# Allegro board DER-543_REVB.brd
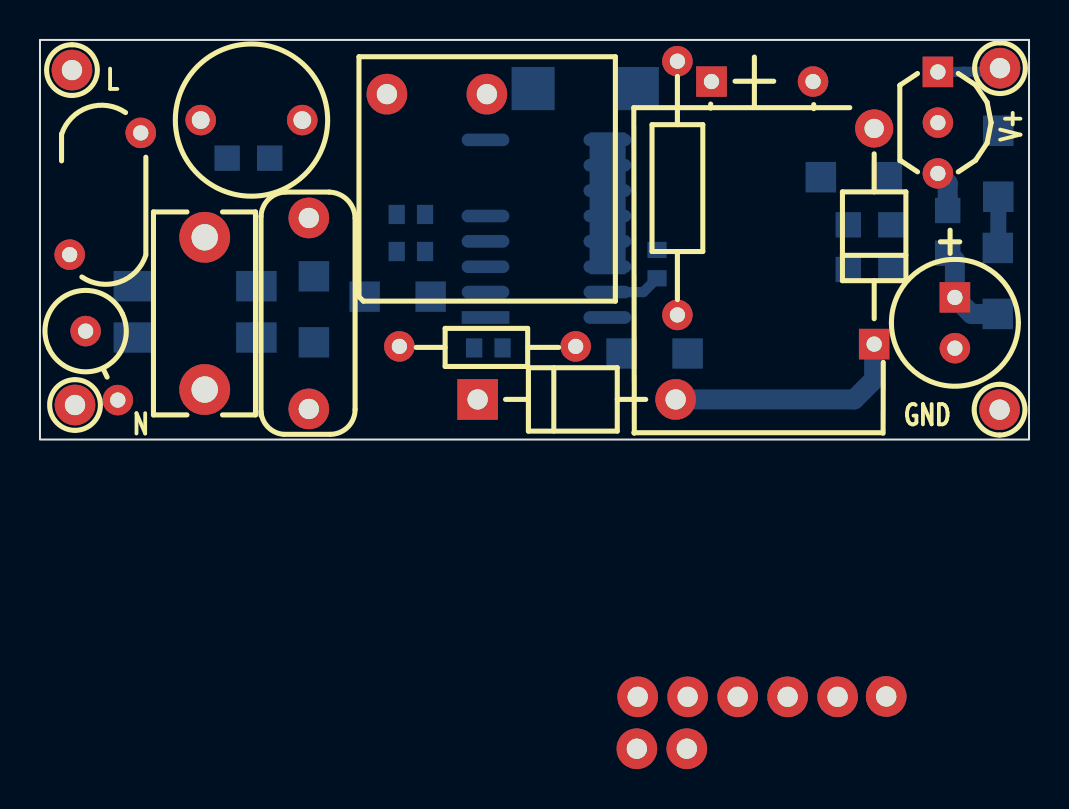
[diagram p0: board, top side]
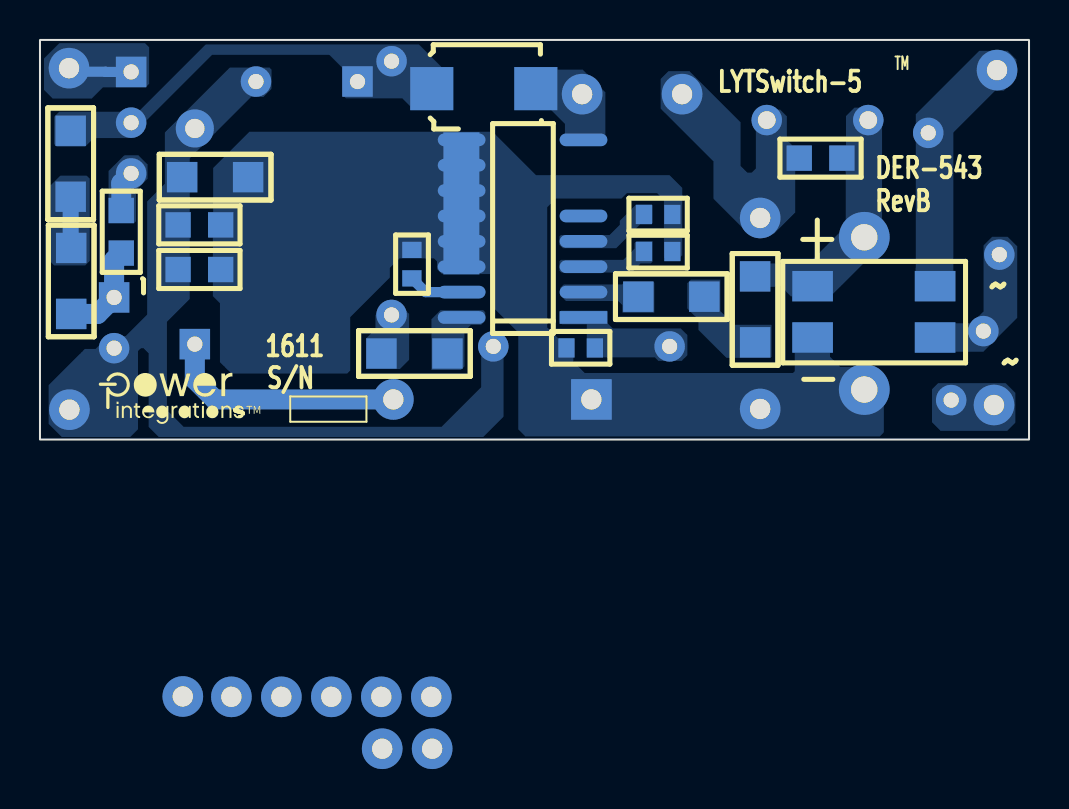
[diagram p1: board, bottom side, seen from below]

Outline 49.48 x 20 mm; copper layers: TOP, BOTTOM. Coordinates in mm from the lower left corner of the outline.
Outline path: rectangle 0,0 49.48,20

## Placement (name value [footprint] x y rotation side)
BR1  B10S-G  [PISMSOIC4]  4.7 5.11 90 bottom
C1  150 nF  [PINPCAPRAD500X200400040]  13.42 11.41 270 top
C2  47 nF  [PI_NP395X200LS300D040]  8.24 10.12 270 top
C4  22 uF  [PIPOLCAPCLYD500LS200040]  33.59 19.42 0 top
C6  2.2 uF  [PISMC0603]  30.87 8.07 90 bottom
C7  180 nF  [PISMC0603]  21.72 4.58 0 bottom
C11  2.2 uF  [PIPOLCAPCYLD250LS100030]  45.77 7.11 270 top
C12  10 uF  [PISMC0805]  42.57 8.51 180 bottom
D1  MURS160T3G  [PISMSMB]  29.88 17.56 180 bottom
D2  1N4001  [PIDV200X110X040DO41]  21.89 2.01 0 top
D3  1N4001  [PIDV200X110X040DO41#2]  41.73 4.78 90 top
F1  5 A  [PI_V_AXIAL_160LS150D030]  2.28 5.43 295 top
L1  3.3 mH  [PICHOKE030DIALS200035]  8.04 15.99 0 top
NOREF  -  []  -150.78 54.23 0 top
NOREF#2  -  []  -228.6 -144.78 0 top
NOREF#3  -  []  0 0 0 top
NOREF#4  -  []  49.48 0 90 top
NOREF#5  -  []  47.09 3.25 180 bottom
Q1  STX13003-AP  [PITO92R100]  44.92 18.4 270 top
R1  10 k  [PISMR0805]  9.36 14.08 0 bottom
R2  2.00 M  [PISMR1206]  13.7 8.17 270 bottom
R3  2.00 M  [PISMR1206]  16.24 7.15 0 bottom
R4  3 k  [PISMR1206]  47.94 15.46 270 bottom
R5  1.6 M  [PI14WVRESD100LS100D030]  31.89 18.94 270 top
R6  3 k  [PISMR1206]  47.92 9.59 270 bottom
R7  1 k  [PISMR0805]  45.41 11.47 270 bottom
R8  1.60 M  [PISMR1206]  29.1 4.31 0 bottom
R9  6.04 k  [PISMR0603]  19.27 9.41 180 bottom
R10  24 k  [PISMR0603]  19.27 11.26 180 bottom
R11  39 k  [PI18WVRESD80LS100D030]  18.58 4.66 0 top
R14  5.49 R  [PISMR1206]  39.07 13.13 0 bottom
R15  10 k  [PISMR0805]  40.44 10.74 0 bottom
RV1  275 Vac  [PIDISC350X160LS210X140040]  1.49 9.25 90 top
T1  EE13  [PI_BOBBIN_EE13V_10P]  17.36 8.79 0 top
TP1  WHT  [PITPKEYSTONE100X100]  1.75 1.73 0 top
TP2  RED  [PITPKEYSTONE100X100]  48.03 18.59 0 top
TP3  WHT  [PITPKEYSTONE100X100]  1.6 18.49 0 top
TP4  BLK  [PITPKEYSTONE100X100]  48.01 1.49 0 top
U1  LYT5225D  [PI_SMD_SO_14-16P_SHORT9-14]  22.29 6.11 90 bottom

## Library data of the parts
BR1 = DIODE BRIDGE_~~+-: alternate symbols: (pi_sm_soic4_slot)
C1 C2 C6 C7 C12 = CAP NP
C4 = CAP POL: alternate symbols: (pipolcapclyd500ls200040630lh)
C11 = CAP POL: alternate symbols: (pipolcapcyld250ls100030h)
D1 = DIODE
D2 D3 = DIODE: alternate symbols: (pidax475x125040do41,pidv200x110x040do41wbead,pidax390x125040do41)
F1 = FUSE
L1 = INDUCTOR: alternate symbols: (pi_choke_450hx375ls197d030_h)
Q1 = NPN_ECB: alternate symbols: (PIT092100)
R1-R4 R6-R10 R14 R15 = R
R5 = R: alternate symbols: (pi14wvresd100ls200d030,pi14wresd100ls400d030,pi14wresd100ls500d030)
R11 = R: alternate symbols: (pi18wresd080ls300d030)
RV1 = VARISTOR
T1 = BEE13/10PINS/GENERIC
TP1-TP4 = TESTPOINT
U1 = LYTSW-5_SO-16

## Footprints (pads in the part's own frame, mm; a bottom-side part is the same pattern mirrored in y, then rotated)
PI14WVRESD100LS100D030
  round 1.524 hole 0.762: 1(0,0) 2(12.7,0)
PI18WVRESD80LS100D030
  round 1.524 hole 0.762: 1(-0.6,0) 2(8.22,0)
PI_BOBBIN_EE13V_10P
  round 2.032 hole 1.016: 1(12.548,-21.666) 2(15.047,-21.666) 3(17.549,-21.666) 4(20.048,-21.666) 5(22.548,-21.666) 6(15.004,-24.265) 7(12.504,-24.265) 8(5.001,8.501) 9(24.978,-21.648) 10(0,8.501)
PI_NP395X200LS300D040
  round 2.54 hole 1.321: 1(0,0) 2(7.62,0)
PI_SMD_SO_14-16P_SHORT9-14
  rect 0.635x2.388 smd: 1(0,0)
  oval 0.635x2.388 smd: 2(1.27,0) 3(2.54,0) 4(3.81,0) 5(5.08,0) 8(8.89,0) 9(8.89,6.096) 10(7.62,6.096) 11(6.35,6.096) 12(5.08,6.096) 13(3.81,6.096) 14(2.54,6.096) 15(1.27,6.096) 16(0,6.096)
PI_V_AXIAL_160LS150D030
  round 1.524 hole 0.762: 1(0,0) 2(3.81,0)
PICHOKE030DIALS200035
  round 1.524 hole 0.889: 1(0,0) 2(5.08,0)
PIDISC350X160LS210X140040
  round 1.524 hole 0.762: 1(0,0) 2(6.096,-3.556)
PIDV200X110X040DO41
  rect 2.032x2.032 hole 1.016: 1(0,0)
  round 2.032 hole 1.016: 2(9.906,0)
PIDV200X110X040DO41#2
  rect 1.524x1.524 hole 0.762: 1(0,0)
  round 1.905 hole 0.965: 2(10.795,0)
PINPCAPRAD500X200400040
  round 2.032 hole 1.016: 1(0.325,0.025) 2(9.885,0.025)
PIPOLCAPCLYD500LS200040
  rect 1.524x1.524 hole 0.762: 1(0,-1.5)
  round 1.524 hole 0.762: 2(5.08,-1.5)
PIPOLCAPCYLD250LS100030
  rect 1.524x1.524 hole 0.762: 1(0,0)
  round 1.524 hole 0.762: 2(2.54,0)
PISMC0603
  rect 0.813x0.965 smd: 1(0,0) 2(1.422,0)
PISMC0805
  rect 1.27x1.27 smd: 1(0,0) 2(2.134,0)
PISMR0603
  rect 0.813x0.965 smd: 1(0,0) 2(1.422,0)
PISMR0805
  rect 1.27x1.27 smd: 1(0,0) 2(2.134,0)
PISMR1206
  rect 1.524x1.524 smd: 1(0,0) 2(3.302,0)
PISMSMB
  rect 2.159x2.159 smd: 1(0,0) 2(5.207,0)
PISMSOIC4
  rect 1.524x2.032 smd: 1(0,0) 2(2.571,0) 3(2.571,6.129) 4(0,6.129)
PITO92R100
  rect 1.524x1.524 hole 0.762: 1(0,0)
  round 1.524 hole 0.762: 2(2.54,0) 3(5.08,0)
PITPKEYSTONE100X100
  round 2.032 hole 1.016: 1(0,0)

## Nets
GND: BR1.4 C1.2 C2.2 C6.2 C7.2 C12.2 D2.1 R9.2 R10.2 R14.1 R15.1 U1.9(S) U1.10(SOURCE10) U1.11(SOURCE11) U1.12(SOURCE12) U1.13(SOURCE13) U1.14(SOURCE14)
N3973903: BR1.2 RV1.2 TP3.1
N3973993: BR1.3 C2.1 L1.1 R1.1 R2.1
N3974133: C4.1 D1.1 Q1.2(COLLECTOR) R4.1 R5.1
N3975245: C1.1 L1.2 R1.2 T1.10
N3976866: F1.2 TP1.1
N3988573: C7.1 R11.1 U1.1(FB)
N3988655: R10.1 U1.4(DS)
N3988764: R9.1 U1.3(DO)
N4093437: BR1.1 F1.1 RV1.1
N4116147: C6.1 U1.15(BP)
N4143937: R2.2 R3.1
N4145625: R3.2 U1.2(L)
N4152865: D1.2 T1.8 U1.8(D)
N4154298: C4.2 C11.2 C12.1 D3.2 R11.2 R14.2 R15.2 TP4.1
N4154621: R8.1 U1.16(OC)
N4279554: Q1.1(EMITTER) TP2.1
N4283675: C11.1 R6.2 R7.2
N4283879: Q1.3(BASE) R7.1
N4293995: D2.2 D3.1
N4302369: R4.2 R6.1
N4302480: R5.2 R8.2

Pads without a net: T1 1 2 3 4 5 6 7 9; U1 5

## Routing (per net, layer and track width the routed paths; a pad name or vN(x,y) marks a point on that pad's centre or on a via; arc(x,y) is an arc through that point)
N4116147: length 2.8
  BOTTOM w0.508: C6.1 30.19,7.38 U1.15
N4279554: length 3
  BOTTOM w0.508: Q1.1 46.19,18.4 46.2,18.41 47.95,18.41
N4283675: length 4.9
  BOTTOM w1: R7.2 45.77,8.97 C11.1 46.6,6.29 R6.2
N4283879: length 2.1
  BOTTOM w1: R7.1 45.41,12.83 Q1.3
N4293995: length 12.1
  BOTTOM w1: D2.2 40.73,2.01 41.73,3.01 D3.1
N4302369: length 2.6
  BOTTOM w0.8: R4.2 47.94,9.61 R6.1

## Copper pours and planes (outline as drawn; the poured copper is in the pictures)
GND on BOTTOM (solid shape): 29.3,8.27 27.5,8.27 27.5,15.38 29.3,15.38
GND on BOTTOM: 7.47,0.15 7.26,0.36 7.26,2.82 8.08,3.63 9.45,3.63 9.96,4.14 9.96,5.46 10.29,5.79 11.66,5.79 11.72,5.73 11.72,3.42 11.81,3.33 22.23,3.33 22.8,3.9 22.8,4.81 23.01,5.03 23.52,5.03 24.1,5.61 24.1,11.62 23.67,12.06 20.39,12.06 20.12,12.33 18.61,12.33 18.26,11.99 18.26,9.14 18.14,9.02 17.55,9.02 17.35,9.22 17.35,12.6 17.98,13.23 24.66,13.23 26.84,15.41 39,15.41 40.82,13.59 40.82,10.44 40.83,10.43 40.83,7.18 40.47,6.82 40.47,3.87 39.9,3.3 34.11,3.3 33.96,3.45 33.96,6.12 31.98,8.1 31.98,8.59 31.5,9.07 29.77,9.07 29.62,8.92 29.62,8.53 29.39,8.31 29.39,8.28 26.94,8.28 26.73,8.08 26.73,6.54 25.55,5.36 25.55,0.51 25.2,0.15
N3973903 on BOTTOM: 2.49,19.46 5.66,16.28 5.66,8.61 5.68,8.6 5.68,7.06 3.96,7.06 3.78,7.24 3.78,15.37 1.69,17.46 1.26,17.46 0.64,18.08 0.64,19.02 1.07,19.46
N3973993 on BOTTOM: 11.02,8.81 9.17,10.67 9.17,13.41 9.32,13.56 9.63,13.56 9.83,13.77 9.83,14.43 9.73,14.53 9.27,14.53 9.16,14.64 9.16,16.19 8.74,16.61 7.7,16.61 7.35,16.27 7.35,10.66 7.37,10.64 7.37,9.73 9.93,7.16 11.91,7.16 12.4,7.65 14.25,7.65 14.38,7.77 14.38,8.81
N3974133 on BOTTOM: 30.91,16.64 29.74,16.64 29.72,16.66 29.59,16.66 29.41,16.84 29.41,18.67 30.52,19.77 41.19,19.77 44.55,16.41 48.51,16.41 48.77,16.15 48.77,14.78 48.64,14.66 47.22,14.66 46.79,15.09 45.03,15.09 40.87,19.25 35,19.25 34.34,18.59 34.34,17.25 34.17,17.08 31.35,17.08
N3975245 on BOTTOM: 13.67,16.13 13.67,13.56 13.87,13.36 14.1,13.36 14.43,13.69 14.43,15.88 16.99,18.44 18.03,18.44 18.43,18.05 18.43,16.56 15.79,13.92 15.79,12.05 14.05,10.31 12.75,10.31 11.7,11.37 11.7,13.42 11.61,13.51 11.15,13.51 10.97,13.69 10.97,14.43 11.1,14.55 11.67,14.55 12.12,15 12.12,16.18 12.45,16.51 13.28,16.51
N3976866 on BOTTOM: 1.09,0.43 0.69,0.84 0.69,2.34 1.17,2.82 4.55,2.82 4.85,2.51 4.85,0.86 4.42,0.43
N3988573 on BOTTOM: 17.42,5.56 20.83,5.56 21.11,5.84 21.11,6.45 23.39,6.45 23.5,6.35 23.5,5.89 23.37,5.77 22.12,5.77 22.12,4.17 22.07,4.11 18.72,4.11 18.54,3.94 17.37,3.94 17.09,4.22 17.09,5.23
N3988655 on BOTTOM: 18.87,11.76 19.66,11.76 20.47,10.95 20.47,10.74 20.98,10.24 23.42,10.24 23.5,10.16 23.5,9.75 23.32,9.58 20.65,9.58 19.46,10.77 18.9,10.77 18.82,10.85 18.82,11.71
N3988764 on BOTTOM: 19.89,8.36 19.43,8.81 18.92,8.81 18.82,8.92 18.82,9.91 18.85,9.93 19.63,9.93 19.74,9.83 19.74,9.55 20.29,8.99 23.42,8.99 23.5,8.92 23.5,8.46 23.39,8.36
N4093437 on BOTTOM: 1.84,10.15 2.27,9.72 2.27,6.41 2.87,5.82 5.64,5.82 5.7,5.75 5.7,4.5 5.6,4.39 2.29,4.39 0.59,6.09 0.59,9.67 1.07,10.15
N4143937 on BOTTOM: 12.9,5.74 14.76,5.74 15.44,6.43 15.44,8 16.92,8 17.09,7.82 17.09,6.55 16.54,5.99 16.54,5.49 15.14,4.09 12.93,4.09 12.88,4.14 12.88,5.71
N4145625 on BOTTOM: 18.77,7.87 20.24,7.87 20.36,7.76 23.28,7.76 23.44,7.59 23.44,7.21 23.16,6.93 20.55,6.93 20.35,6.73 20.35,6.38 20.32,6.35 18.75,6.35 18.75,7.85
N4152865 on BOTTOM: 25.65,18.52 25.65,16.66 24.08,16.66 23.22,15.8 23.22,14.83 21.3,14.83 21.2,14.94 21.2,17.39 22.33,18.52
N4154298 on BOTTOM: 27.3,0.13 26.29,1.14 26.29,4.8 26.82,5.33 27.13,5.33 27.41,5.05 27.41,2.62 29.39,0.64 42.29,0.64 43.13,1.47 43.13,5.89 41.99,7.04 41.99,14.07 38.91,17.14 38.3,17.14 37.9,17.55 37.9,18.52 38,18.62 39.98,18.62 43.23,15.37 43.23,12.8 44.12,11.91 44.12,6.25 45.19,5.18 46.05,5.18 46.7,4.53 47.23,4.53 49.05,2.72 49.05,0.79 48.39,0.13 44.96,0.13 44.58,0.51 44.58,4.42 44.42,4.57 44.3,4.57 44.04,4.32 44.04,0.64 43.54,0.13
N4154621 on BOTTOM: 27.3,6.48 29.44,6.48 29.9,6.02 29.9,3.48 28.42,3.48 28.24,3.66 28.24,5.41 27.91,5.74 27.41,5.74 27.2,5.94 27.2,6.38
N4279554 on BOTTOM: 44.22,19.84 48.51,19.84 49.28,19.08 49.28,17.5 48.84,17.07 46.89,17.07 46.33,17.63 44.17,17.63 44.17,17.65 44.02,17.81 44.02,19.63
N4283879 on BOTTOM: 44.55,14.22 45.26,14.22 46.05,13.44 46.05,10.82 44.78,10.82 44.68,10.92 44.68,12.47 44.09,13.06 44.09,13.77
N4302369 on BOTTOM: 47.14,13.21 48.46,13.21 48.95,12.73 48.95,8.89 48.77,8.71 47.22,8.71 46.99,8.94 46.99,13.06
N4302480 on BOTTOM: 33.15,5.08 33.15,3.53 31.47,3.53 31.01,3.99 31.01,6.29 31.45,6.72 32.21,6.72 32.7,6.23 32.7,5.53

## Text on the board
Ref Des/Silkscreen Bottom: TM | DER-543 | RevB | LYTSwitch-5 | S/N | 1611
Ref Des/Silkscreen Top: L | N | GND | V+
PEN17: 13   MATERIAL FR4 COPPER 2oz THICKNESS 0.047"
User.5: FIGURE | SIZE | 30.0 | 35.0 | 38.0 | 40.0 | 52.0 | DRILL CHART: TOP to BOTTOM | ALL UNITS ARE IN MILS | QTY | 16 | 2 | 1 | 18
